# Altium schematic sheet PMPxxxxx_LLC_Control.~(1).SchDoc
size 431 x 279 mm; Date: Not shown in title block; ApprovedBy: Not shown in title block; CheckedBy: Not shown in title block; Author: Not shown in title block; CompanyName: Not shown in title block; Engineer: Not shown in title block; Organization: Not shown in title block; Address1: Not shown in title block; Address2: Not shown in title block; Address3: Not shown in title block; Address4: Not shown in title block; DocumentNumber: 1; Revision: Use project parameter SCH_Rev; SheetNumber: 4; SheetTotal: 4; PageSetup: Record=PageOptions¦CenterHorizontal=True¦CenterVertical=True¦PrintScale=1.00¦XCorrection=1.00¦YCorrection=1.00¦PrintKind=0¦BorderSize=5000000¦LeftOffset=0¦BottomOffset=0¦Orientation=2¦PaperLength=1000¦PaperWidth=1000¦Scale=100¦PaperSource=15¦PrintQuality=600¦MediaType=1¦DitherType=10¦PaperKind=Letter¦PrintScaleMode=1
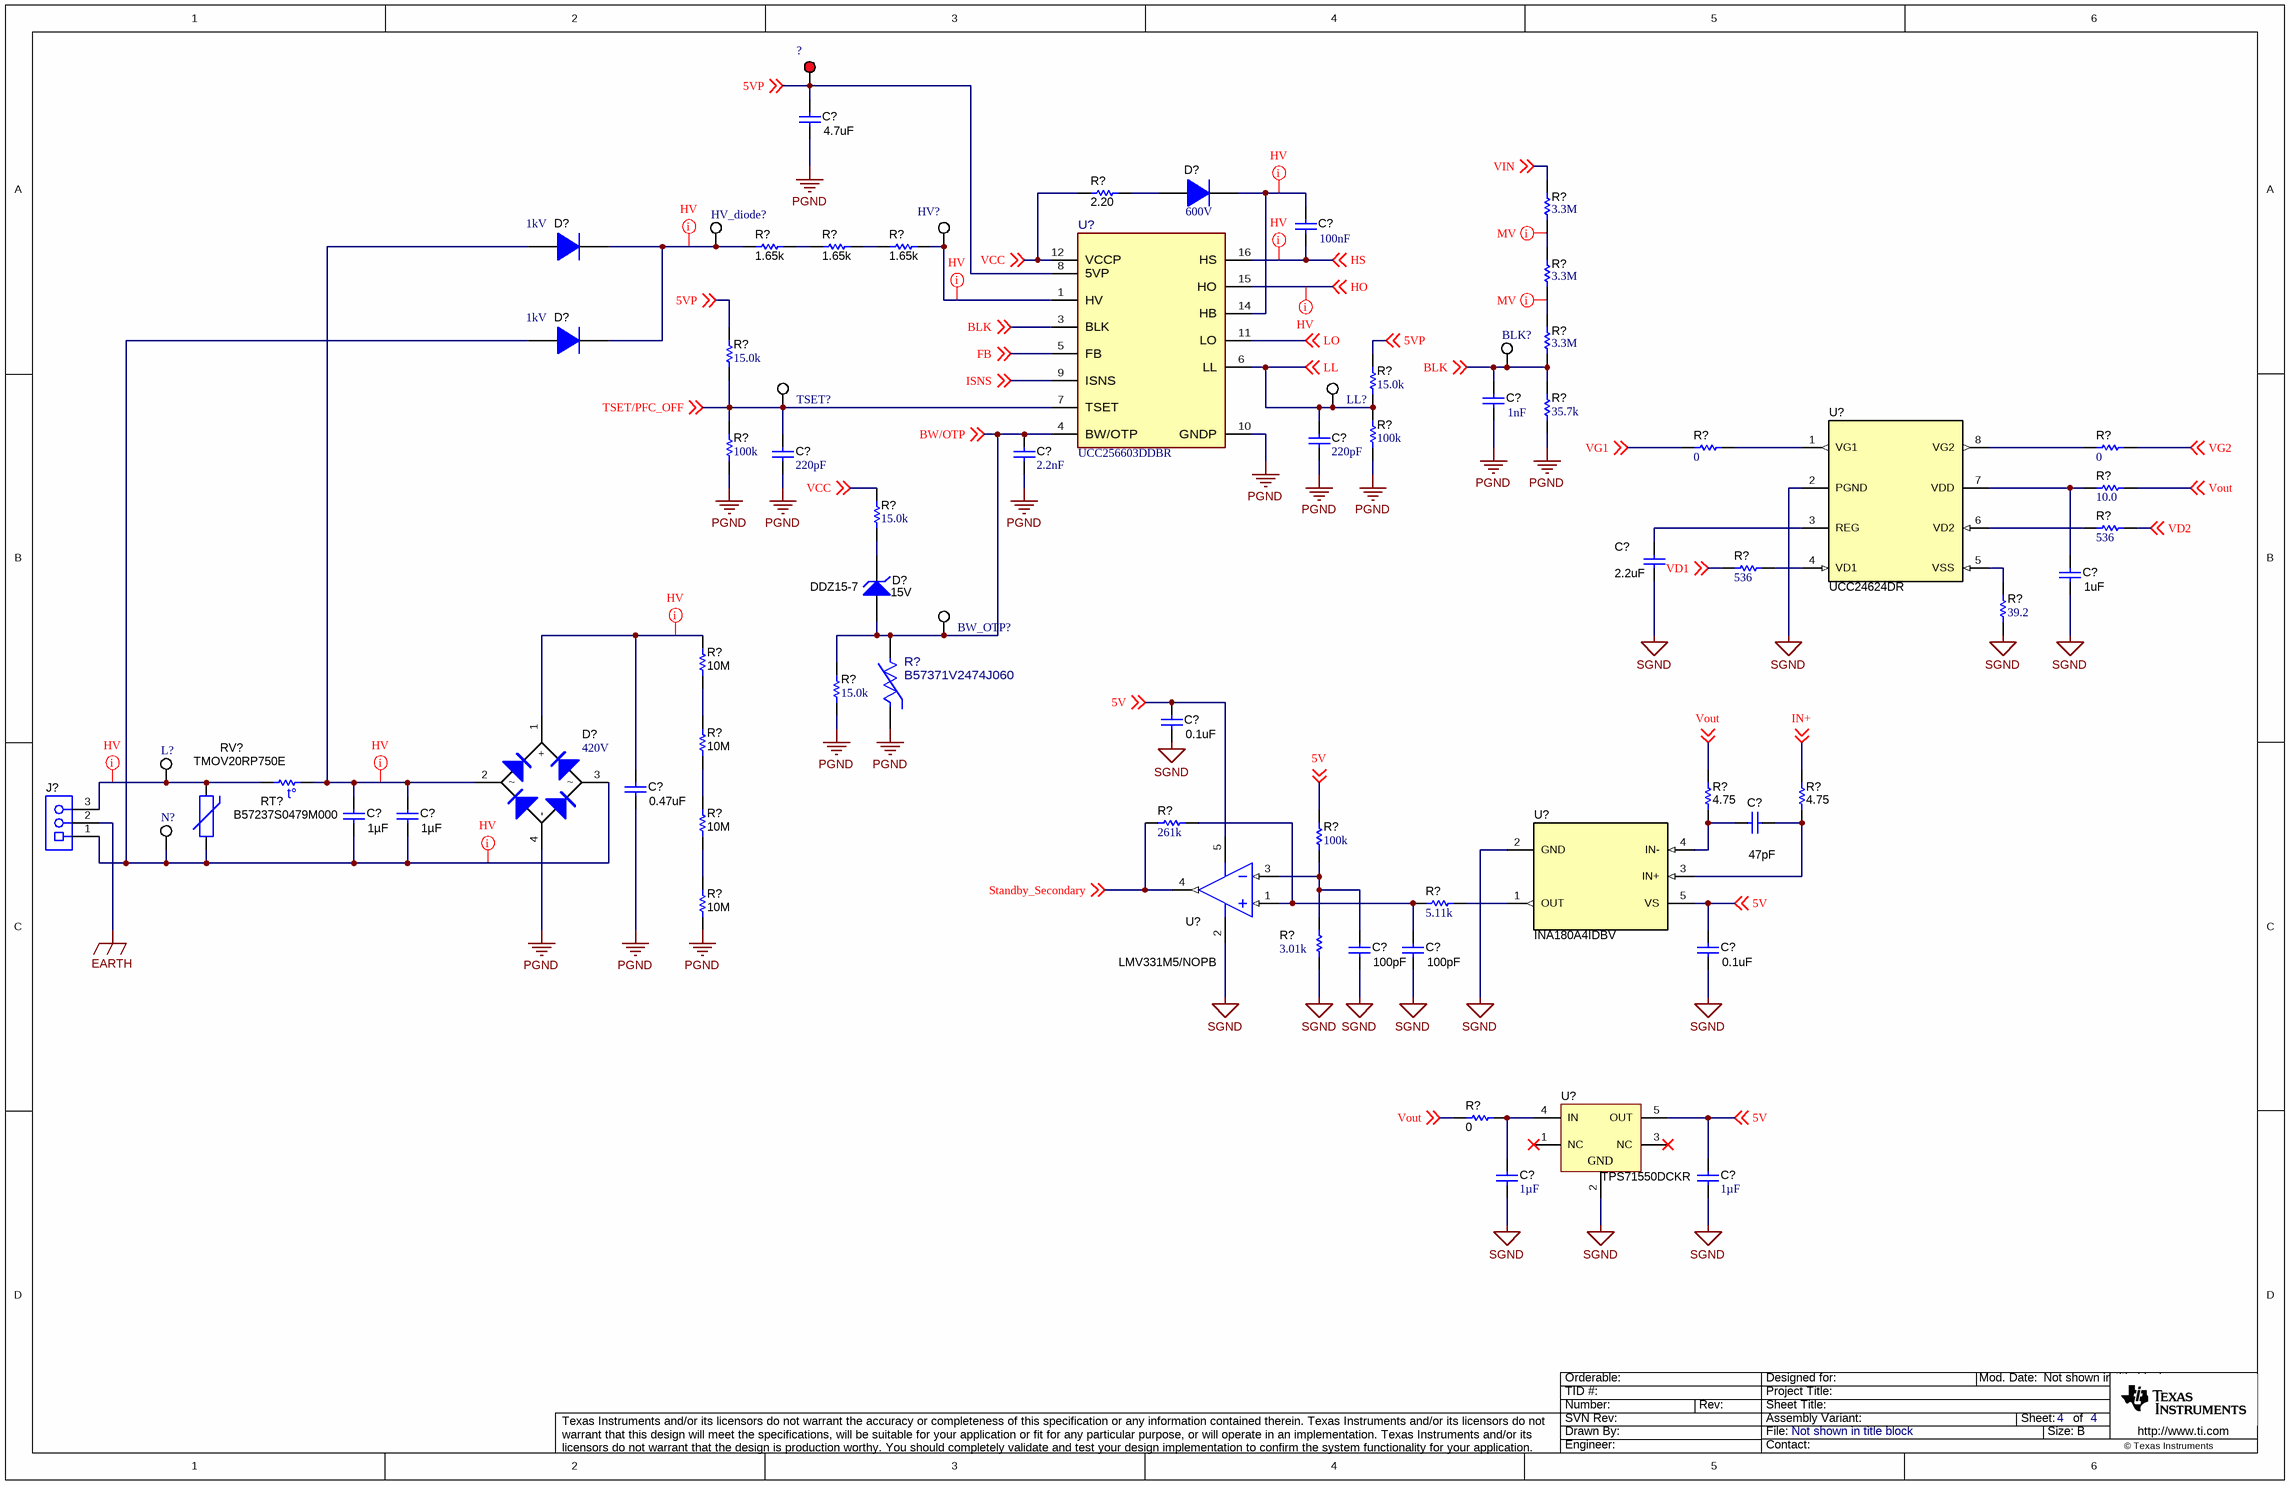
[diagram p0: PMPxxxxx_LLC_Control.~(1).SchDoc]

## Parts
(Parts that share a designator on the sheet are numbered #1, #2 ... from top to bottom, then left to right.)
?  5010  [Keystone5010]  (value not drawn)
BLK?  5012  [Keystone5012]  (value not drawn)
BW_OTP?  5012  [Keystone5012]  (value not drawn)
C?#1  ValueDisplayed: 4.7uF  [1206L]  (hidden comment: C3216X7R1E475K085AB)
C?#2  Cap_F: 100nF  [1206_180L]  (hidden comment: GRM31C5C1E104JA01L)
C?#3  Cap_F: 1nF  [0402L]  (hidden comment: 04025C102JAT2A)
C?#4  Cap_F: 220pF  [0603]  (hidden comment: C0603X221K5RACTU)
C?#5  Cap_F: 220pF  [0603]  (hidden comment: C0603X221K5RACTU)
C?#6  Cap_F: 2.2nF  [0603]  (hidden comment: C0603X222K5RACTU)
C?#7  ValueDisplayed: 2.2uF  [0805L]  (hidden comment: C2012X7R1V225K085AC)
C?#8  ValueDisplayed: 1uF  [0603L]  (hidden comment: GRM188R71C105KE15D)
C?#9  ValueDisplayed: 0.1uF  [0402L]  (hidden comment: GRM155R61C104KA88D)
C?#10  ValueDisplayed: 0.47uF  [B32922_17.5mm]  (hidden comment: B32922C3474K)
C?#11  ValueDisplayed: 1µF  [R46_2650x1000x1850]  (hidden comment: R46KN410000P0M)
C?#12  ValueDisplayed: 1µF  [R46_2650x1000x1850]  (hidden comment: R46KN410000P0M)
C?#13  ValueDisplayed: 47pF  [1206L]  (hidden comment: 12067A470JAT2A)
C?#14  ValueDisplayed: 100pF  [0402L]  (hidden comment: GRM1555C1H101JA01D)
C?#15  ValueDisplayed: 100pF  [0402L]  (hidden comment: GRM1555C1H101JA01D)
C?#16  ValueDisplayed: 0.1uF  [0402L]  (hidden comment: GRM155R61E104KA87D)
C?#17  Cap_F: 1µF  [0603L]  (hidden comment: EMK107B7105KA-T)
C?#18  Cap_F: 1µF  [0603L]  (hidden comment: EMK107B7105KA-T)
D?#1  Vr_V: 600V  [SMAF]  (hidden comment: ES1JAF)
D?#2  Vr_V: 1kV  [DO-41]  (hidden comment: 1N4007-E3/73)
D?#3  Vr_V: 1kV  [DO-41]  (hidden comment: 1N4007-E3/73)
D?#4  DDZ15-7  value 15V  [SOD-123]
D?#5  Vr_V: 420V  [GBU]  (hidden comment: GBU8J-BP)
HV?  5012  [Keystone5012]  (value not drawn)
HV_diode?  5012  [Keystone5012]  (value not drawn)
J?  ED120/3DS  [On-Shore_ED120_3DS]  (value not drawn)
L?  5012  [Keystone5012]  (value not drawn)
LL?  5012  [Keystone5012]  (value not drawn)
N?  5012  [Keystone5012]  (value not drawn)
R?#1  ValueDisplayed: 2.20  [0603L]  (hidden comment: ERJ-3RQF2R2V)
R?#2  Res_ohm: 3.3M  [FP-KTR18EZPF3304_1206-MFG]  (hidden comment: KTR18EZPF3304)
R?#3  ValueDisplayed: 1.65k  [1206L]  (hidden comment: CRCW12061K65FKEA)
R?#4  ValueDisplayed: 1.65k  [1206L]  (hidden comment: CRCW12061K65FKEA)
R?#5  ValueDisplayed: 1.65k  [1206L]  (hidden comment: CRCW12061K65FKEA)
R?#6  Res_ohm: 3.3M  [FP-KTR18EZPF3304_1206-MFG]  (hidden comment: KTR18EZPF3304)
R?#7  Res_ohm: 3.3M  [FP-KTR18EZPF3304_1206-MFG]  (hidden comment: KTR18EZPF3304)
R?#8  ValueDisplayed: 15.0k  [0603]  (hidden comment: RT0603BRD0715KL)
R?#9  ValueDisplayed: 15.0k  [0603]  (hidden comment: RT0603BRD0715KL)
R?#10  ValueDisplayed: 35.7k  [0603]  (hidden comment: RT0603BRD0735K7L)
R?#11  ValueDisplayed: 100k  [0603]  (hidden comment: RT0603BRD07100KL)
R?#12  ValueDisplayed: 100k  [0603]  (hidden comment: RT0603BRD07100KL)
R?#13  ValueDisplayed: 0  [0603L]  (hidden comment: RC0603JR-070RL)
R?#14  ValueDisplayed: 0  [0603L]  (hidden comment: RC0603JR-070RL)
R?#15  ValueDisplayed: 10.0  [0603L]  (hidden comment: RC0603FR-0710RL)
R?#16  ValueDisplayed: 15.0k  [0603]  (hidden comment: RG1608P-153-B-T5)
R?#17  ValueDisplayed: 536  [0603L]  (hidden comment: RT0603BRD07536RL)
R?#18  ValueDisplayed: 536  [0603L]  (hidden comment: RT0603BRD07536RL)
R?#19  ValueDisplayed: 39.2  [0603L]  (hidden comment: RC0603FR-0739R2L)
R?#20  ValueDisplayed: 10M  [1206]  (hidden comment: CRCW120610M0JNEA)
R?#21  ValueDisplayed: 15.0k  [0603]  (hidden comment: RG1608P-153-B-T5)
R?#22  B57371V2474J060  [FP-B57371V2474J060_0603-MFG]
R?#23  ValueDisplayed: 10M  [1206]  (hidden comment: CRCW120610M0JNEA)
R?#24  ValueDisplayed: 4.75  [0402L]  (hidden comment: CRCW04024R75FKED)
R?#25  ValueDisplayed: 4.75  [0402L]  (hidden comment: CRCW04024R75FKED)
R?#26  ValueDisplayed: 10M  [1206]  (hidden comment: CRCW120610M0JNEA)
R?#27  ValueDisplayed: 261k  [0402L]  (hidden comment: CRCW0402261KFKED)
R?#28  ValueDisplayed: 100k  [0402L]  (hidden comment: ERJ-2RKF1003X)
R?#29  ValueDisplayed: 10M  [1206]  (hidden comment: CRCW120610M0JNEA)
R?#30  ValueDisplayed: 5.11k  [0402L]  (hidden comment: CRCW04025K11FKED)
R?#31  ValueDisplayed: 3.01k  [0402L]  (hidden comment: CRCW04023K01FKED)
R?#32  ValueDisplayed: 0  [0603L]  (hidden comment: RC0603JR-070RL)
RT?  B57237S0479M000  [S237]
RV?  TMOV20RP750E  [Littelfuse_TMOV20RP750E]
TSET?  5012  [Keystone5012]  (value not drawn)
U?#1  UCC256603DDBR  [DDB0014A-MFG]
U?#2  UCC24624DR  [D0008A_N]
U?#3  LMV331M5/NOPB  [DBV0005A_N]
U?#4  INA180A4IDBV  [DBV0005A_L]
U?#5  TPS71550DCKR  [DCK0005A_L]

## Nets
EARTH: J?.2
PGND: C?#1.2 C?#3.2 C?#4.2 C?#5.2 C?#6.2 C?#10.2 D?#5.4(-) R?#10.1 R?#11.1 R?#12.1 R?#21.1 R?#22.1 R?#29.2 U?#1.10(GNDP)
SGND: C?#7.2 C?#8.2 C?#9.2 C?#14.1 C?#15.2 C?#16.2 C?#17.2 C?#18.2 R?#19.2 R?#31.1 U?#2.2(PGND) U?#3.2(V-) U?#4.2(GND) U?#5.2(GND)
5V: C?#9.1 C?#16.1 C?#18.1 R?#28.2 U?#3.5(V+) U?#4.5(VS) U?#5.5(OUT) ; off-sheet 5V
5VP: ?.1 C?#1.1 R?#8.2 R?#9.2 U?#1.8(5VP) ; off-sheet 5VP
BLK: BLK?.1 C?#3.1 R?#7.1 R?#10.2 U?#1.3(BLK) ; off-sheet BLK
BW/OTP: BW_OTP?.1 C?#6.1 D?#4.2(A) R?#21.2 R?#22.2 U?#1.4(BW/OTP) ; off-sheet BW/OTP
FB: U?#1.5(FB) ; off-sheet FB
HO: U?#1.15(HO) ; off-sheet HO
HS: C?#2.2 U?#1.16(HS) ; off-sheet HS
IN+: R?#25.2 ; off-sheet IN+
ISNS: U?#1.9(ISNS) ; off-sheet ISNS
LL: C?#4.1 LL?.1 R?#9.1 R?#11.2 U?#1.6(LL) ; off-sheet LL
LO: U?#1.11(LO) ; off-sheet LO
Standby_Secondary: R?#27.1 U?#3.4(OUT) ; off-sheet Standby_Secondary
TSET/PFC_OFF: C?#5.1 R?#8.1 R?#12.2 TSET?.1 U?#1.7(TSET) ; off-sheet TSET/PFC_OFF
VCC: R?#1.1 R?#16.2 U?#1.12(VCCP) ; off-sheet VCC
VD1: R?#18.2 ; off-sheet VD1
VD2: R?#17.1 ; off-sheet VD2
VG1: R?#13.1 ; off-sheet VG1
VG2: R?#14.2 ; off-sheet VG2
VIN: R?#2.2 ; off-sheet VIN
Vout: R?#15.2 R?#24.2 R?#32.1 ; off-sheet Vout
NetC?#2_1: C?#2.1 D?#1.1(K) U?#1.14(HB)
NetC?#7_1: C?#7.1 U?#2.3(REG)
NetC?#8_1: C?#8.1 R?#15.1 U?#2.7(VDD)
NetC?#10_1: C?#10.1 D?#5.1(+) R?#20.1
NetC?#11_1: C?#11.1 C?#12.1 D?#2.2(A) D?#5.2 RT?.2
NetC?#11_2: C?#11.2 C?#12.2 D?#3.2(A) D?#5.3 J?.1 N?.1 RV?.1
NetC?#13_1: C?#13.1 R?#24.1 U?#4.4(IN-)
NetC?#13_2: C?#13.2 R?#25.1 U?#4.3(IN+)
NetC?#14_2: C?#14.2 R?#28.1 R?#31.2 U?#3.3(IN-)
NetC?#15_1: C?#15.1 R?#27.2 R?#30.1 U?#3.1(IN+)
NetC?#17_1: C?#17.1 R?#32.2 U?#5.4(IN)
NetD?#1_2: D?#1.2(A) R?#1.2
NetD?#2_1: D?#2.1(K) D?#3.1(K) HV_diode?.1 R?#3.1
NetD?#4_1: D?#4.1(K) R?#16.1
NetHV?_1: HV?.1 R?#5.2 U?#1.1(HV)
NetJ?_3: J?.3 L?.1 RT?.1 RV?.2
NetR?#2_1: R?#2.1 R?#6.2
NetR?#3_2: R?#3.2 R?#4.1
NetR?#4_2: R?#4.2 R?#5.1
NetR?#6_1: R?#6.1 R?#7.2
NetR?#13_2: R?#13.2 U?#2.1(VG1)
NetR?#14_1: R?#14.1 U?#2.8(VG2)
NetR?#17_2: R?#17.2 U?#2.6(VD2)
NetR?#18_1: R?#18.1 U?#2.4(VD1)
NetR?#19_1: R?#19.1 U?#2.5(VSS)
NetR?#20_2: R?#20.2 R?#23.1
NetR?#23_2: R?#23.2 R?#26.1
NetR?#26_2: R?#26.2 R?#29.1
NetR?#30_2: R?#30.2 U?#4.1(OUT)

Not connected (* = marked no-connect by the designer): U?#5 1(NC)* 3(NC)*

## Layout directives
net class MV: NetR?#2_1, NetR?#6_1
net class HV: HO, HS, NetC?#2_1, NetC?#10_1, NetC?#11_1, NetC?#11_2, NetD?#2_1, NetHV?_1, NetJ?_3

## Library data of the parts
? = CMP-0055147-2: Test Point, Multipurpose, Red, TH; Manufacturer: Keystone Electronics; CNHeader: FALSE; Green_Lifecycle: Active; Green_REACh: Passed; ContactFinish: Silver; CT: TRUE
BLK? BW_OTP? HV? HV_diode? L? LL? N? TSET? = CMP-0055149-2: Test Point, Multipurpose, White, TH; Manufacturer: Keystone Electronics; CNHeader: FALSE; Green_Lifecycle: Active; Green_REACh: Passed; ContactFinish: Silver; CT: TRUE
C?#1 = CMP-0008693-2: CAP, CERM, 4.7 uF, 25 V, +/- 10%, X7R, 1206; Manufacturer: TDK; TaMin_C: -55°C; Polarized: N; SizeAreaWB_mm2: 10.92; Value1: Unknown; U/M: EA; Value: 4.7uF; TaMax_C: 125°C; SizeZ_mm: 1.35; SizeX_mm: 3.2; SizeY_mm: 1.6; Cap_Case: 1206; Value2: 25V; SizeArea_mm2: 5.12; CompType: Capacitor; Cap_F: 4.7µF; AEC Category: Q200
C?#2 = CMP-0064950-2: CAP, CERM, 0.1 uF, 25 V,+/- 5%, C0G/NP0, 1206; Manufacturer: MuRata; TaMin_C: -55°C; Polarized: N; SizeAreaWB_mm2: 10.92; Value1: Unknown; U/M: EA; Value: 0.1uF; TaMax_C: 125°C; SizeZ_mm: 1.8; SizeX_mm: 3.2; SizeY_mm: 1.6; Cap_Case: 1206; Value2: 25V; SizeArea_mm2: 5.12; AEC Category: Q200
C?#3 = CMP-0861060-1: CAP, CERM, 1000 pF, 50 V,+/- 5%, X7R, 0402; Manufacturer: AVX; Value2: 50V; SizeY_mm: 0.5; AEC Category: Q200; Polarized: N; Green_Lifecycle: Active; SizeAreaWB_mm2: 3; ValueDisplayed: 1000pF; Cap_Case: 0402; Value: 1000pF; TaMin_C: -55°C; U/M: EA; Green_REACh: Passed; SizeZ_mm: 0.6; SizeX_mm: 1; TaMax_C: 125°C
C?#4 C?#5 = CMP-0006982-4: CAP, CERM, 220 pF, 50 V, +/- 10%, X7R, 0603; Manufacturer: Kemet; TaMin_C: -55°C; Polarized: N; SizeAreaWB_mm2: 4.68; Value1: Unknown; U/M: EA; Value: 220pF; TaMax_C: 125°C; SizeZ_mm: 1; SizeX_mm: 1.6; SizeY_mm: 0.8; Value2: 50V; SizeArea_mm2: 1.28; AEC Category: Q200
C?#6 = CMP-0006983-4: CAP, CERM, 2200 pF, 50 V, +/- 10%, X7R, 0603; Manufacturer: Kemet; TaMin_C: -55°C; Polarized: N; SizeAreaWB_mm2: 4.68; Value1: Unknown; U/M: EA; Value: 2200pF; TaMax_C: 125°C; SizeZ_mm: 1; SizeX_mm: 1.6; SizeY_mm: 0.8; Value2: 50V; SizeArea_mm2: 1.28; AEC Category: Q200
C?#7 = CMP-0007883-2: CAP, CERM, 2.2 uF, 35 V, +/- 10%, X7R, 0805; Manufacturer: TDK; TaMin_C: -55°C; Polarized: N; SizeAreaWB_mm2: 6.75; Value1: Unknown; U/M: EA; Value: 2.2uF; TaMax_C: 125°C; SizeZ_mm: 1.45; SizeX_mm: 2; SizeY_mm: 1.25; Cap_Case: 0805; Value2: 35V; SizeArea_mm2: 2.5; CompType: Capacitor; Cap_F: 2.2µF; AEC Category: Q200
C?#8 = CMP-0007380-4: CAP, CERM, 1 uF, 16 V, +/- 10%, X7R, 0603; Manufacturer: MuRata; TaMin_C: -55°C; Polarized: N; SizeAreaWB_mm2: 4.68; Value1: Unknown; U/M: EA; Value: 1uF; TaMax_C: 125°C; SizeZ_mm: 1; SizeX_mm: 1.6; SizeY_mm: 0.8; Cap_Case: 0603; Value2: 16V; SizeArea_mm2: 1.28; CompType: Capacitor; Cap_F: 1µF; AEC Category: Q200
C?#9 = CMP-0006591-2: CAP, CERM, 0.1 uF, 16 V, +/- 10%, X5R, 0402; Manufacturer: MuRata; TaMin_C: -55°C; Polarized: N; SizeAreaWB_mm2: 3; Value1: Unknown; U/M: EA; Value: 0.1uF; TaMax_C: 85°C; SizeZ_mm: 0.6; SizeX_mm: 1; SizeY_mm: 0.5; Cap_Case: 0402; Value2: 16V; CompType: Capacitor; Cap_F: 100nF; AEC Category: Q200
C?#10 = CMP-0012412-3: CAP, Film, 0.47 uF, 630 V, +/- 10%, TH; Manufacturer: TDK; Polarized: N; SizeAreaWB_mm2: 220; Value1: Unknown; Value: 0.47uF; TaMax_C: 110°C; SizeZ_mm: 17.5; SizeX_mm: 18; SizeY_mm: 9; Value2: 630V; SizeArea_mm2: 162; CompType: Capacitor; Cap_F: 470nF; AEC Category: Q200
C?#11 C?#12 = CMP-0074805-2: CAP, Film, 1 µF, X2 275 VAC, +/- 20%, TH; Manufacturer: Kemet; TaMin_C: -40°C; Polarized: N; SizeAreaWB_mm2: 342.0; Value: 1uF; TaMax_C: 110°C; VAC_X: 275; SizeZ_mm: 18.6; SizeX_mm: 26.5; SizeY_mm: 10.0; Cap_Case: 26.5x10x18.5mm; Value2: 560V; SizeArea_mm2: 265.0; CompType: Capacitor; AEC Category: Q200
C?#13 = CMP-0008568-2: CAP, CERM, 47 pF, 500 V, +/- 5%, C0G/NP0, 1206; Manufacturer: AVX; TaMin_C: -55°C; Polarized: N; SizeAreaWB_mm2: 10.92; Value1: Unknown; U/M: EA; Value: 47pF; TaMax_C: 125°C; SizeZ_mm: 1.35; SizeX_mm: 3.2; SizeY_mm: 1.6; Cap_Case: 1206; Value2: 500V; SizeArea_mm2: 5.12; CompType: Capacitor; AEC Category: Q200
C?#14 C?#15 = CMP-0006410-2: CAP, CERM, 100 pF, 50 V, +/- 5%, C0G/NP0, 0402; Manufacturer: MuRata; TaMin_C: -55°C; Polarized: N; SizeAreaWB_mm2: 3; Value1: Unknown; U/M: EA; Value: 100pF; TaMax_C: 125°C; SizeZ_mm: 0.6; SizeX_mm: 1; SizeY_mm: 0.5; Cap_Case: 0402; Value2: 50V; CompType: Capacitor; AEC Category: Q200
C?#16 = CMP-0006607-2: CAP, CERM, 0.1 uF, 25 V, +/- 10%, X5R, 0402; Manufacturer: MuRata; TaMin_C: -55°C; Polarized: N; SizeAreaWB_mm2: 3; Value1: Unknown; U/M: EA; Value: 0.1uF; TaMax_C: 85°C; SizeZ_mm: 0.6; SizeX_mm: 1; SizeY_mm: 0.5; Cap_Case: 0402; Value2: 25V; CompType: Capacitor; Cap_F: 100nF; AEC Category: Q200
C?#17 C?#18 = CMP-0007120-4: CAP, CERM, 1 uF, 16 V, +/- 10%, X7R, 0603; Manufacturer: Taiyo Yuden; TaMin_C: -55°C; Polarized: N; SizeAreaWB_mm2: 4.68; Value1: Unknown; U/M: EA; Value: 1uF; TaMax_C: 85°C; SizeZ_mm: 1; SizeX_mm: 1.6; SizeY_mm: 0.8; Cap_Case: 0603; Value2: 16V; SizeArea_mm2: 1.28; AEC Category: Q200
D?#1 = CMP-0029162-2: Diode, Ultrafast, 600 V, 1 A, AEC-Q101, SMAF; Manufacturer: Fairchild Semiconductor; Io_A: 1A; Green_Lifecycle: Not Set; SizeAreaWB_mm2: 19.95; Green_REACh: Incomplete; TJmax_C: 150°C; Value: 600V; SizeZ_mm: 1; SizeX_mm: 4.7; SizeY_mm: 2.5; Vf_V: 1.7V; SizeArea_mm2: 11.75; AEC Qualified: Y; AEC Category: Q101
D?#2 D?#3 = CMP-0029188-2: Diode, P-N, 1000 V, 1 A, TH; Manufacturer: Vishay-Semiconductor; Io_A: 1A; SizeAreaWB_mm2: 43.424; TJmax_C: 150°C; Value: 1000V; SizeZ_mm: 23.4; SizeX_mm: 7.2; SizeY_mm: 2.72; Vf_V: 1.1V; SizeArea_mm2: 19.584; AEC Qualified: N; AEC Category: Q101
D?#4 = CMP-0085135-1: Diode, Zener, 15 V, 500 mW, SOD-123; Manufacturer: Diodes Inc.; SizeAreaWB_mm2: 13.095; SizeArea_mm2: 6.545; SizeY_mm: 1.7; AEC Qualified: N; SizeZ_mm: 1.35; Value1: 0.5W; SizeX_mm: 3.85; Power_W: 500mW; RJA_CperW: 425; AEC Category: Q101
D?#5 = CMP-0029222-3: Diode, Switching-Bridge, 420 V, 8 A, TH; Manufacturer: Micro Commercial Components; Io_A: 8A; Green_Lifecycle: Not Set; SizeAreaWB_mm2: 130.5915; Green_REACh: Incomplete; TJmax_C: 175°C; Value: 420V; SizeZ_mm: 21.55; SizeX_mm: 22.05; SizeY_mm: 3.43; Vf_V: 1V; SizeArea_mm2: 75.6315; AEC Category: Q101
J? = CMP-0074911-1: Terminal Block, 5.08 mm, 3x1, Brass, TH; Manufacturer: On-Shore Technology; Cert_VDE: Y; CNHeader: False; Current_A: 15A; Green_Lifecycle: Not Set; Shrouded: N; Gender: Female; Green_REACh: Incomplete; Voltage_V: 300V; Row_Count: 1; Pitch_mm: 5.08; CT: True
R?#1 = CMP-0022711-2: RES, 2.20, 1%, 0.1 W, 0603; Manufacturer: Panasonic; Power_W: 100mW; TempCo: 200 ppm/C; Value_Code: 2R20; U/M: EA; Value: 2.20; Res_ohm: 2.2; SizeX_mm: 1.6; SizeY_mm: 0.8; SizeZ_mm: 1; Value2: 0.1W; SizeArea_mm2: 1.28; CompType: Resistor; AEC Category: Q200
R?#2 R?#6 R?#7 = CMP-0087456-2: 3.3 MOhms ±1% 0.25W, 1/4W Chip Resistor 1206 (3216 Metric) Automotive AEC-Q200, High Voltage Thick Film; Manufacturer: Rohm Semiconductor; AEC Qualified: Yes; Power_W: 250mW; SizeZ_mm: 0.65mm; AEC Grade: Grade 0; TempCo: 100ppm/°C; VDC_V: 500V
R?#3-R?#5 = CMP-0016708-3: RES, 1.65 k, 1%, 0.25 W, AEC-Q200 Grade 0, 1206; Manufacturer: Vishay-Dale; Power_W: 250mW; TempCo: 100 ppm/C; Value_Code: 1k65; Value: 1.65k; EIA_Code: E96; SizeX_mm: 3.2; SizeY_mm: 1.6; SizeZ_mm: 1.35; Value2: 0.25W; SizeArea_mm2: 5.12; CompType: Resistor; AEC Qualified: Y; VDC_V: 200V; AEC Category: Q200; AEC Grade: 0
R?#8 R?#9 = CMP-0023780-3: RES, 15.0 k, 0.1%, 0.1 W, 0603; Manufacturer: Yageo America; Power_W: 100mW; TempCo: 25 ppm/C; Value_Code: 15k0; U/M: EA; Value: 15.0k; EIA_Code: E192; Res_ohm: 15k; SizeX_mm: 1.6; SizeY_mm: 0.8; SizeZ_mm: 1; Value2: 0.1W; SizeArea_mm2: 1.28; VDC_V: 75V; AEC Category: Q200
R?#10 = CMP-0024147-3: RES, 35.7 k, 0.1%, 0.1 W, 0603; Manufacturer: Yageo America; Power_W: 100mW; TempCo: 25 ppm/C; Value_Code: 35k7; U/M: EA; Value: 35.7k; EIA_Code: E192; SizeX_mm: 1.6; SizeY_mm: 0.8; SizeZ_mm: 1; Value2: 0.1W; SizeArea_mm2: 1.28; VDC_V: 75V; AEC Category: Q200
R?#11 R?#12 = CMP-0023630-3: RES, 100 k, 0.1%, 0.1 W, 0603; Manufacturer: Yageo America; Power_W: 100mW; TempCo: 25 ppm/C; U/M: EA; Value: 100k; EIA_Code: E192; SizeX_mm: 1.6; SizeY_mm: 0.8; SizeZ_mm: 1; Value2: 0.1W; SizeArea_mm2: 1.28; VDC_V: 75V; AEC Category: Q200
R?#13 R?#14 = CMP-0025885-5: RES, 0, 5%, 0.1 W, 0603; Manufacturer: Yageo; Power_W: 100mW; TempCo: 200 ppm/C; Value_Code: 0000; Value: 0; EIA_Code: E24; SizeX_mm: 1.6; SizeZ_mm: 1; Value2: 0.1W; SizeArea_mm2: 1.28; AEC Qualified: N; VDC_V: 75V; AEC Category: Q200; SizeY_mm: 0.8; SizeAreaWB_mm2: 4.68
R?#15 = CMP-0022751-4: RES, 10.0, 1%, 0.1 W, 0603; Manufacturer: Yageo; Power_W: 100mW; TempCo: 100 ppm/C; Value_Code: 10R0; Value: 10.0; EIA_Code: E96; Res_ohm: 10; SizeX_mm: 1.6; SizeY_mm: 0.8; SizeZ_mm: 1; Value2: 0.1W; SizeArea_mm2: 1.28; AEC Qualified: N; VDC_V: 75V; AEC Category: Q200; SizeAreaWB_mm2: 4.68
R?#16 R?#21 = CMP-0023441-3: RES, 15.0 k, 0.1%, 0.1 W, 0603; Manufacturer: Susumu Co Ltd; Power_W: 100mW; TempCo: 25 ppm/C; Value_Code: 15k0; U/M: EA; Value: 15.0k; EIA_Code: E192; Res_ohm: 15k; SizeX_mm: 1.6; SizeY_mm: 0.8; SizeZ_mm: 1; Value2: 0.1W; SizeArea_mm2: 1.28; VDC_V: 75V; AEC Category: Q200
R?#17 R?#18 = CMP-0024324-2: RES, 536, 0.1%, 0.1 W, 0603; Manufacturer: Yageo America; Power_W: 100mW; TempCo: 25 ppm/C; Value_Code: 536R; U/M: EA; Value: 536; EIA_Code: E192; SizeX_mm: 1.6; SizeY_mm: 0.8; SizeZ_mm: 1; Value2: 0.1W; SizeArea_mm2: 1.28; VDC_V: 75V; AEC Category: Q200
R?#19 = CMP-0023074-4: RES, 39.2, 1%, 0.1 W, 0603; Manufacturer: Yageo; Power_W: 100mW; TempCo: 100 ppm/C; Value_Code: 39R2; Value: 39.2; EIA_Code: E96; SizeX_mm: 1.6; SizeY_mm: 0.8; SizeZ_mm: 1; Value2: 0.1W; SizeArea_mm2: 1.28; AEC Qualified: N; VDC_V: 75V; AEC Category: Q200; SizeAreaWB_mm2: 4.68
R?#20 R?#23 R?#26 R?#29 = CMP-0018577-3: RES, 10 M, 5%, 0.25 W, AEC-Q200 Grade 0, 1206; Manufacturer: Vishay-Dale; Power_W: 250mW; TempCo: 200 ppm/C; Value_Code: 10M0; Value: 10Meg; EIA_Code: E24; SizeX_mm: 3.2; SizeY_mm: 1.6; SizeZ_mm: 1.35; Value2: 0.25W; SizeArea_mm2: 5.12; AEC Qualified: Y; VDC_V: 200V; AEC Category: Q200; AEC Grade: 0
R?#22 = CMP-0096703-1: NTC Thermistor 470k 0603 (1608 Metric); Manufacturer: TDK; AEC Qualified: No; Res_ohm: 470kΩ; Power_W: 180mW; B 25 50: 4386K; B 25 100: 4480K; SizeZ_mm: 0.9mm; B 25 85: 4455K; B Tolerance: 3%; Tolerance_%: 5%
R?#24 R?#25 = CMP-0026432-2: RES, 4.75, 1%, 0.063 W, AEC-Q200 Grade 0, 0402; Manufacturer: Vishay-Dale; Power_W: 63mW; TempCo: 100 ppm/C; Value_Code: 4R75; Value: 4.75; EIA_Code: E96; SizeX_mm: 1; SizeY_mm: 0.5; SizeZ_mm: 0.6; Value2: 0.063W; CompType: Resistor; AEC Qualified: Y; VDC_V: 50V; AEC Category: Q200; AEC Grade: 0
R?#27 = CMP-0026203-2: RES, 261 k, 1%, 0.063 W, AEC-Q200 Grade 0, 0402; Manufacturer: Vishay-Dale; Power_W: 63mW; TempCo: 100 ppm/C; Value: 261k; EIA_Code: E96; SizeX_mm: 1; SizeY_mm: 0.5; SizeZ_mm: 0.6; Value2: 0.063W; AEC Qualified: Y; VDC_V: 50V; AEC Category: Q200; AEC Grade: 0
R?#28 = CMP-0026659-2: RES, 100 k, 1%, 0.1 W, 0402; Manufacturer: Panasonic; Power_W: 100mW; TempCo: 100 ppm/C; U/M: EA; Value: 100k; EIA_Code: E96; SizeX_mm: 1; SizeY_mm: 0.5; SizeZ_mm: 0.6; Value2: 0.1W; AEC Qualified: Yes; VDC_V: 50V; AEC Category: Q200; AEC Grade: 0
R?#30 = CMP-0026463-2: RES, 5.11 k, 1%, 0.063 W, AEC-Q200 Grade 0, 0402; Manufacturer: Vishay-Dale; Power_W: 63mW; TempCo: 100 ppm/C; Value_Code: 5k11; Value: 5.11k; EIA_Code: E96; SizeX_mm: 1; SizeY_mm: 0.5; SizeZ_mm: 0.6; Value2: 0.063W; AEC Qualified: Y; VDC_V: 50V; AEC Category: Q200; AEC Grade: 0
R?#31 = CMP-0026329-2: RES, 3.01 k, 1%, 0.063 W, AEC-Q200 Grade 0, 0402; Manufacturer: Vishay-Dale; Power_W: 63mW; TempCo: 100 ppm/C; Value_Code: 3k01; Value: 3.01k; EIA_Code: E96; SizeX_mm: 1; SizeY_mm: 0.5; SizeZ_mm: 0.6; Value2: 0.063W; AEC Qualified: Y; VDC_V: 50V; AEC Category: Q200; AEC Grade: 0
R?#32 = CMP-0025885-5: RES, 0, 5%, 0.1 W, 0603; Manufacturer: Yageo; Power_W: 100mW; TempCo: 200 ppm/C; Value_Code: 0000; Value: 0; EIA_Code: E24; SizeX_mm: 1.6; SizeZ_mm: 1; Value2: 0.1W; SizeArea_mm2: 1.28; CompType: Resistor; AEC Qualified: N; VDC_V: 75V; AEC Category: Q200; SizeY_mm: 0.8; SizeAreaWB_mm2: 4.68
RT? = CMP-0002554-2: Thermistor NTC, 4.70 ohm, 20%, 15x7mm; Manufacturer: TDK; TaMax_C: 170°C; SizeX_mm: 15; SizeY_mm: 7.5; TaMin_C: -55°C; Power_W: 3.1W; SizeZ_mm: 47; Value: 4.7; SizeArea_mm2: 112.5; SizeAreaWB_mm2: 161.5; U/M: EA
RV? = CMP-0080568-2: VARISTOR 1200V 10KA DISC 20MM; Manufacturer: Littelfuse; SizeZ_mm: 28; SizeX_mm: 21; SizeY_mm: 13; SizeArea_mm2: 273; SizeAreaWB_mm2: 345
U?#1 = CMP-0095299-1: 750kHz Wide VIN/VOUT Range LLC Controller Optimized for Light Load Efficiency; Manufacturer: Texas Instruments; Number Of Outputs: 2; TaMax_C: +125°C; Output Type: Other; TJmax_C: +150°C; AEC Qualified: No; Standoff Height: 0.1mm; TaMin_C: -40°C; SizeZ_mm: 1.75mm; Switching Frequency: 30-750kHz; Max Supply Voltage: 18.5V
U?#2 = CMP-0079610-1: High Performance Synchronous Rectifier Driver for LLC Resonant Converter, D0008A (SOIC-8); Alternate Manufacturer: Texas Instruments; SizeAreaWB_mm2: 56.58; SizeZ_mm: 1.75; SizeX_mm: 4.9; SizeY_mm: 6.2; SizeArea_mm2: 30.38; CompType: IC; AEC Qualified: N; AEC Category: Q200
U?#3 = CMP-0068476-2: Single General Purpose, Low Voltage, Tiny Pack Comparator, 5-pin SOT-23, Pb-Free; Manufacturer: Texas Instruments; PowerWise: Y; PackageTopMarking: C12*XTT; CompType: Amplifiers; AEC Category: Q200; AEC Qualified: N; SizeAreaWB_mm2: 14.82; SizeArea_mm2: 8.12; SizeX_mm: 2.8; SizeY_mm: 2.9; SizeZ_mm: 1.45
U?#4 = CMP-0013052-2: Low- and High-Side Measurement, Multichannel, Voltage Output, Current-Sense Amplifier, DBV0005A (SOT-5); Manufacturer: Texas Instruments; SizeX_mm: 2.8; SizeY_mm: 2.9; CompType: IC; SizeZ_mm: 1.45; SizeArea_mm2: 8.12; SizeAreaWB_mm2: 14.82; U/M: EA
U?#5 = CMP-0035742-2: Single Output LDO, 50 mA, Fixed 5 V Output, 3 to 24 V Input, 5-pin SC70 (DCK), -40 to 85 degC, Green (RoHS & no Sb/Br); Manufacturer: Texas Instruments; Iq(Typ)(mA): 0.003; Accuracy(%): 4; Vout Adj(Min)(V): 5; SubFamily: Single Channel LDO; Vin(Max)(V): 24; Vin(Min)(V): 3; Vdo(Typ)(mV): 415; Iout(Max)(A): 0.05; AEC Category: Q200; AEC Qualified: N; CompType: IC; SizeAreaWB_mm2: 9.3; SizeArea_mm2: 4.2; SizeX_mm: 2.1; SizeY_mm: 2.0; SizeZ_mm: 1.1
